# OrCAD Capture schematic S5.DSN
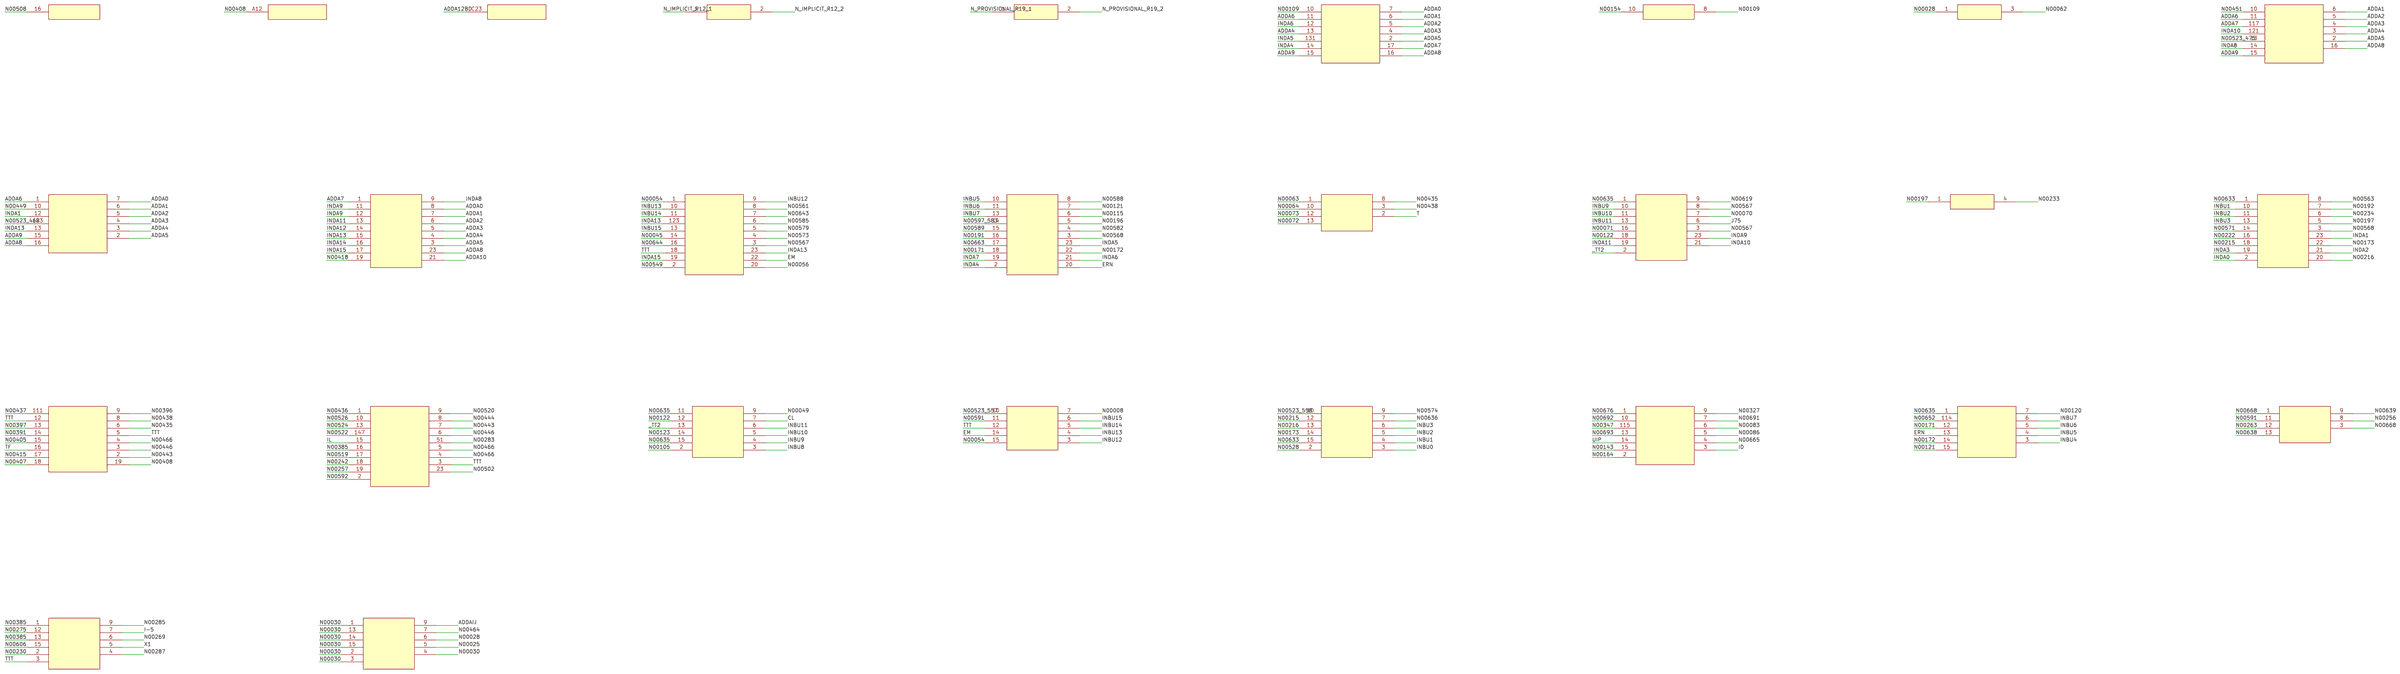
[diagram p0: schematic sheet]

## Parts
J1  CONNECTOR
P1  CONNECTOR
P2  CONNECTOR
R12  1K00
R19  1K05
U4  74F00
U5  74F240
U8  74F151
U10  2148
U17  74F32
U19  74F02
U21  2148
U22  2148
U35  UNKNOWN
U36  74F181
U37  74F181
U49  74F181
U50  74F181
U53  UNKNOWN
U54  54321
U56  74F194
U58  74F194
U59  74F194
U60  74F182
U61  74F194
U63  74F74
U64  74F157

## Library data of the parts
J1 = OBS_J1
P1 = OBS_P1
P2 = OBS_P2
R12 = OBS_R12
R19 = OBS_R19
U4 = OBS_U4
U5 = OBS_U5
U8 = OBS_U8
U10 = OBS_U10
U17 = OBS_U17
U19 = OBS_U19
U21 = OBS_U21
U22 = OBS_U22
U35 = OBS_U35
U36 = OBS_U36
U37 = OBS_U37
U49 = OBS_U49
U50 = OBS_U50
U53 = OBS_U53
U54 = OBS_U54
U56 = OBS_U56
U58 = OBS_U58
U59 = OBS_U59
U60 = OBS_U60
U61 = OBS_U61
U63 = OBS_U63
U64 = OBS_U64

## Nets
_TT2: U49.2 U56.13
ADDA0: U10.7 U22.7 U35.8
ADDA1: U10.6 U21.6 U22.6 U35.7
ADDA2: U10.5 U21.5 U22.5 U35.6
ADDA3: U10.4 U21.4 U22.4 U35.5
ADDA4: U10.13 U21.3 U22.3 U35.4
ADDA5: U10.2 U21.2 U22.2 U35.3
ADDA6: U10.11 U21.11 U22.1
ADDA7: U10.17 U21.117 U35.1
ADDA8: U10.16 U21.16 U22.16 U35.23
ADDA9: U10.15 U21.15 U22.15
ADDA10: U35.21
ADDA12BD: P2.C23
ADDAIJ: U8.9
CL: U56.7
EM: U36.22 U58.14
ERN: U37.20 U61.13
I-5: U64.7
ID: U60.3
IL: U54.15
INBU0: U59.3
INBU1: U50.10 U59.4
INBU2: U50.11 U59.5
INBU3: U50.13 U59.6
INBU4: U61.3
INBU5: U37.10 U61.4
INBU6: U37.11 U61.5
INBU7: U37.13 U61.6
INBU8: U56.3
INBU9: U49.10 U56.4
INBU10: U49.11 U56.5
INBU11: U49.13 U56.6
INBU12: U36.9 U58.3
INBU13: U36.10 U58.4
INBU14: U36.11 U58.5
INBU15: U36.13 U58.6
INDA0: U50.2
INDA1: U22.12 U50.23
INDA2: U50.21
INDA3: U50.19
INDA4: U10.14 U37.2
INDA5: U10.131 U37.23
INDA6: U10.12 U37.21
INDA7: U37.19
INDA8: U21.14 U35.9
INDA9: U35.11 U35.12 U49.23
INDA10: U21.121 U49.21
INDA11: U35.13 U49.19
INDA12: U35.14
INDA13: U22.13 U35.15 U36.23 U36.123
INDA14: U35.16
INDA15: U35.17 U36.19
J75: U49.6
N00523_468: U22.123
N00523_475: U21.13
N00523_557: U58.10
N00523_558: U59.10
N00597_583: U37.14
N_IMPLICIT_R12_1: R12.1
N_IMPLICIT_R12_2: R12.2
N_PROVISIONAL_R19_1: R19.1
N_PROVISIONAL_R19_2: R19.2
T: U4.2
TF: U53.16
TTT: U36.18 U53.5 U53.12 U54.3 U58.12 U64.3
UIP: U60.14
X1: U64.5
N00028: U8.6 U19.1
N00030: U8.1 U8.2 U8.3 U8.4 U8.13 U8.14 U8.15
N00054: U36.1 U58.15
N00109: U10.10 U17.8
N00121: U37.7 U61.15
N00122: U49.18 U56.12
N00171: U37.18 U61.12
N00172: U37.22 U61.14
N00173: U50.22 U59.14
N00197: U5.1 U50.5
N00215: U50.18 U59.12
N00216: U50.20 U59.13
N00385: U54.16 U64.1 U64.13
N00408: P1.A12 U53.19
N00435: U4.8 U53.6
N00438: U4.3 U53.8
N00443: U53.2 U54.7
N00446: U53.3 U54.6
N00466: U53.4 U54.4 U54.5
N00567: U36.3 U49.3 U49.8
N00568: U37.3 U50.3
N00591: U58.11 U63.11
N00633: U50.1 U59.15
N00635: U49.1 U56.11 U56.15 U61.1
N00668: U63.1 U63.3

Not connected (* = marked no-connect by the designer): J1 16; U4 1 10 12 13; U5 4; U8 5 7; U17 10; U19 3; U21 10; U22 10; U35 19; U36 2 4 5 6 7 8 14 16 20; U37 4 5 6 8 15 16 17; U49 7 9 16; U50 6 7 8 14 16; U53 9 13 14 15 17 18 111; U54 1 2 8 9 10 13 17 18 19 23 51 147; U56 2 9 14; U58 7; U59 2 7 9; U60 1 2 4 5 6 7 9 10 13 15 115; U61 7 114; U63 8 9 12 13; U64 2 4 6 9 12 15
